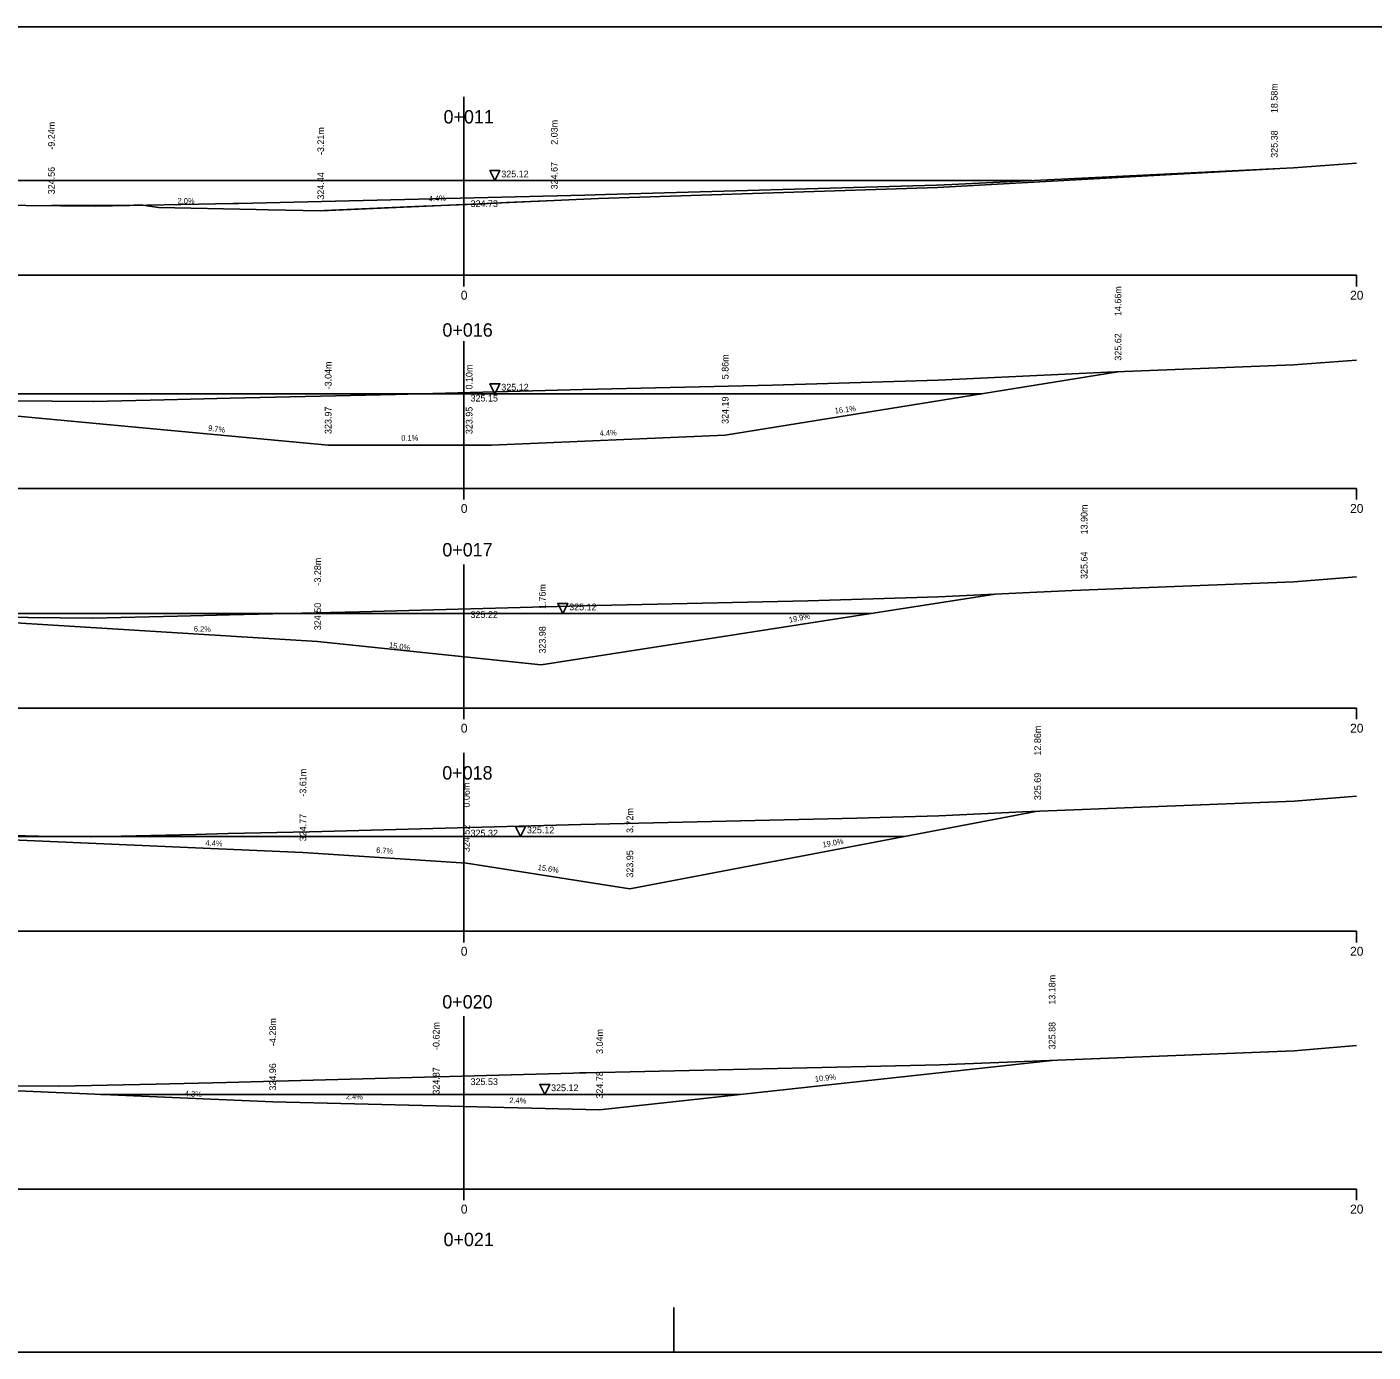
# Model space of a CAD drawing. Extents: x -557877.8 to -557804.3, y -1162285.8 to -1162256.1.
# Drawn here: x -557860.8 to -557830.63, y -1162285.8 to -1162256.1 of the extents above; entities that cross this region are included whole.
import ezdxf

# ---------------------------------------------------------------- set-up
doc = ezdxf.new("R2010")
doc.units = 0
for name, color, linetype in [('16', 7, 'Continuous'), ('21', 7, 'Continuous'), ('28', 7, 'Continuous'), ('59', 7, 'Continuous'), ('Body pricny rez', 7, 'Continuous'), ('Popis pricneho profilu', 7, 'Continuous')]:
    doc.layers.add(name, color=color, linetype=linetype)

msp = doc.modelspace()

# ---------------------------------------------------------------- linework, layer by layer
for p, q in [((-557804.302, -1162256.102), (-557877.802, -1162256.102)), ((-557846.302, -1162285.802), (-557846.302, -1162284.802)), ((-557877.802, -1162285.802), (-557804.302, -1162285.802))]:
    msp.add_line(p, q)
for points in [[(-557871.005, -1162259.545), (-557864.464, -1162260.043), (-557864.118, -1162260.057), (-557862.37, -1162260.09), (-557859.263, -1162260.117), (-557856.183, -1162260.062), (-557856.133, -1162260.062), (-557856.051, -1162260.06), (-557848.291, -1162259.873), (-557847.829, -1162259.856), (-557840.415, -1162259.648), (-557840.07, -1162259.632), (-557832.415, -1162259.263), (-557831.005, -1162259.154)], [(-557860.246, -1162260.103), (-557858.4, -1162260.098), (-557858.196, -1162260.095), (-557857.844, -1162260.15), (-557855.661, -1162260.194), (-557855.389, -1162260.199), (-557854.211, -1162260.223), (-557854.132, -1162260.219), (-557852.105, -1162260.13), (-557850.74, -1162260.071), (-557850.048, -1162260.04), (-557848.979, -1162259.993), (-557847.99, -1162259.95), (-557840.395, -1162259.701), (-557832.845, -1162259.284)], [(-557870.994, -1162259.546), (-557838.275, -1162259.546)], [(-557848.979, -1162259.993), (-557854.211, -1162260.223)], [(-557848.979, -1162259.993), (-557854.211, -1162260.223)], [(-557871.005, -1162263.973), (-557869.084, -1162264.121), (-557863.687, -1162264.471), (-557863.682, -1162264.471), (-557861.146, -1162264.48), (-557859.312, -1162264.494), (-557859.307, -1162264.494), (-557857.717, -1162264.456), (-557856.24, -1162264.425), (-557852.539, -1162264.339), (-557848.349, -1162264.225), (-557844.087, -1162264.128), (-557840.375, -1162264.022), (-557836.581, -1162263.841), (-557832.414, -1162263.676), (-557831.005, -1162263.567)], [(-557845.149, -1162265.249), (-557836.348, -1162263.832)], [(-557854.045, -1162265.475), (-557867.49, -1162264.224)], [(-557866.422, -1162264.324), (-557839.401, -1162264.324)], [(-557850.382, -1162265.478), (-557854.045, -1162265.475)], [(-557850.382, -1162265.478), (-557854.045, -1162265.475)], [(-557850.382, -1162265.478), (-557845.149, -1162265.249)], [(-557850.382, -1162265.478), (-557845.149, -1162265.249)], [(-557871.005, -1162268.839), (-557869.944, -1162268.921), (-557862.864, -1162269.33), (-557862.864, -1162269.33), (-557862.858, -1162269.33), (-557860.77, -1162269.339), (-557859.335, -1162269.35), (-557859.329, -1162269.35), (-557857.423, -1162269.305), (-557856.259, -1162269.28), (-557853.342, -1162269.212), (-557848.362, -1162269.077), (-557843.297, -1162268.961), (-557840.368, -1162268.878), (-557837.376, -1162268.736), (-557832.408, -1162268.539), (-557831.005, -1162268.43)], [(-557849.271, -1162270.399), (-557839.102, -1162268.818)], [(-557854.281, -1162269.873), (-557867.102, -1162269.085)], [(-557864.436, -1162269.249), (-557841.875, -1162269.249)], [(-557849.271, -1162270.399), (-557854.281, -1162269.873)], [(-557871.005, -1162273.756), (-557866.633, -1162274.079), (-557866.633, -1162274.079), (-557866.626, -1162274.079), (-557860.248, -1162274.247), (-557859.367, -1162274.253), (-557859.359, -1162274.253), (-557857.014, -1162274.198), (-557856.286, -1162274.182), (-557854.46, -1162274.14), (-557848.38, -1162273.975), (-557842.196, -1162273.834), (-557840.359, -1162273.781), (-557838.482, -1162273.692), (-557832.4, -1162273.451), (-557831.005, -1162273.343)], [(-557847.285, -1162275.418), (-557838.148, -1162273.682)], [(-557847.285, -1162275.418), (-557838.148, -1162273.682)], [(-557854.611, -1162274.603), (-557866.633, -1162274.079)], [(-557862.728, -1162274.249), (-557841.132, -1162274.249)], [(-557850.948, -1162274.847), (-557854.611, -1162274.603)], [(-557850.948, -1162274.847), (-557854.611, -1162274.603)], [(-557850.948, -1162274.847), (-557847.285, -1162275.418)], [(-557850.948, -1162274.847), (-557847.285, -1162275.418)], [(-557871.005, -1162279.36), (-557864.773, -1162279.805), (-557864.6, -1162279.814), (-557864.591, -1162279.815), (-557864.11, -1162279.821), (-557860.084, -1162279.844), (-557860.076, -1162279.845), (-557857.908, -1162279.794), (-557856.326, -1162279.761), (-557848.559, -1162279.549), (-557848.413, -1162279.546), (-557848.274, -1162279.543), (-557840.34, -1162279.365), (-557839.969, -1162279.351), (-557832.396, -1162279.05), (-557831.005, -1162278.934)], [(-557847.962, -1162280.37), (-557837.823, -1162279.266)], [(-557847.962, -1162280.37), (-557837.823, -1162279.266)], [(-557855.288, -1162280.192), (-557863.955, -1162279.822)], [(-557859.146, -1162280.027), (-557844.812, -1162280.027)], [(-557851.625, -1162280.281), (-557855.288, -1162280.192)], [(-557851.625, -1162280.281), (-557855.288, -1162280.192)], [(-557851.625, -1162280.281), (-557847.962, -1162280.37)], [(-557851.625, -1162280.281), (-557847.962, -1162280.37)]]:
    msp.add_lwpolyline(points)
for points in [[(-557850.309, -1162259.546), (-557850.421, -1162259.321), (-557850.196, -1162259.321)], [(-557850.309, -1162264.324), (-557850.421, -1162264.099), (-557850.196, -1162264.099)], [(-557848.787, -1162269.249), (-557848.9, -1162269.024), (-557848.675, -1162269.024)], [(-557849.734, -1162274.249), (-557849.846, -1162274.024), (-557849.621, -1162274.024)], [(-557849.192, -1162280.027), (-557849.305, -1162279.802), (-557849.08, -1162279.802)]]:
    msp.add_lwpolyline(points, close=True)
at = {"layer": '16'}
for p, q in [((-557871.005, -1162261.666), (-557831.005, -1162261.666)), ((-557871.005, -1162266.444), (-557831.005, -1162266.444)), ((-557871.005, -1162271.369), (-557831.005, -1162271.369)), ((-557871.005, -1162276.369), (-557831.005, -1162276.369)), ((-557871.005, -1162282.147), (-557831.005, -1162282.147))]:
    msp.add_line(p, q, dxfattribs=at)
at = {"layer": '28'}
for p, q in [((-557851.005, -1162257.666), (-557851.005, -1162261.666)), ((-557851.005, -1162263.146), (-557851.005, -1162266.444)), ((-557851.005, -1162268.153), (-557851.005, -1162271.369)), ((-557851.005, -1162272.369), (-557851.005, -1162276.369)), ((-557851.005, -1162278.271), (-557851.005, -1162282.147))]:
    msp.add_line(p, q, dxfattribs=at)
at = {"layer": '59'}
for p, q in [((-557851.005, -1162261.916), (-557851.005, -1162261.666)), ((-557831.005, -1162261.916), (-557831.005, -1162261.666)), ((-557851.005, -1162266.694), (-557851.005, -1162266.444)), ((-557831.005, -1162266.694), (-557831.005, -1162266.444)), ((-557851.005, -1162271.619), (-557851.005, -1162271.369)), ((-557831.005, -1162271.619), (-557831.005, -1162271.369)), ((-557851.005, -1162276.619), (-557851.005, -1162276.369)), ((-557831.005, -1162276.619), (-557831.005, -1162276.369)), ((-557851.005, -1162282.397), (-557851.005, -1162282.147)), ((-557831.005, -1162282.397), (-557831.005, -1162282.147))]:
    msp.add_line(p, q, dxfattribs=at)

# ---------------------------------------------------------------- texts
for s, height, p in [('0+011', 0.3, (-557851.46, -1162258.266)), ('325.12', 0.15, (-557850.166, -1162259.472)), ('0+016', 0.3, (-557851.485, -1162263.044)), ('325.12', 0.15, (-557850.166, -1162264.251)), ('0+017', 0.3, (-557851.487, -1162267.969)), ('325.12', 0.15, (-557848.645, -1162269.176)), ('0+018', 0.3, (-557851.488, -1162272.969)), ('325.12', 0.15, (-557849.591, -1162274.176)), ('0+020', 0.3, (-557851.488, -1162278.102)), ('325.12', 0.15, (-557849.05, -1162279.954)), ('0+021', 0.3, (-557851.46, -1162283.427))]:
    msp.add_text(s, height=height).set_placement(p)
for s, rotation, p in [('16.1%', 6.8723, (-557842.687, -1162264.767)), ('9.7%', 352.9905, (-557856.74, -1162265.151))]:
    msp.add_text(s, height=0.125, rotation=rotation).set_placement(p)
at = {"layer": '16'}
for s, rotation, p in [('2.0%', 358.8604, (-557857.422, -1162260.059)), ('4.4%', 2.5086, (-557851.788, -1162260.016)), ('4.4%', 2.5086, (-557847.959, -1162265.272)), ('0.1%', 359.9393, (-557852.407, -1162265.376)), ('19.9%', 11.2497, (-557843.707, -1162269.455)), ('6.2%', 357.3014, (-557857.057, -1162269.65)), ('15.0%', 351.4967, (-557852.689, -1162270.011)), ('19.0%', 10.7549, (-557842.955, -1162274.495)), ('4.4%', 357.2549, (-557856.797, -1162274.45)), ('6.7%', 356.1861, (-557852.973, -1162274.612)), ('15.6%', 351.1463, (-557849.356, -1162274.995)), ('10.9%', 6.2156, (-557843.133, -1162279.744)), ('4.3%', 357.0992, (-557857.26, -1162280.067)), ('2.4%', 358.6034, (-557853.65, -1162280.132)), ('2.4%', 358.6034, (-557849.987, -1162280.221))]:
    msp.add_text(s, height=0.125, rotation=rotation, dxfattribs=at).set_placement(p)
at = {"layer": '21'}
for s, p in [('0', (-557851.072, -1162262.216)), ('20', (-557831.145, -1162262.216)), ('0', (-557851.072, -1162266.994)), ('20', (-557831.145, -1162266.994)), ('0', (-557851.072, -1162271.919)), ('20', (-557831.145, -1162271.919)), ('0', (-557851.072, -1162276.919)), ('20', (-557831.145, -1162276.919)), ('0', (-557851.072, -1162282.697)), ('20', (-557831.145, -1162282.697))]:
    msp.add_text(s, height=0.2, dxfattribs=at).set_placement(p)
at = {"layer": '59'}
for s, p in [('324.73', (-557850.855, -1162260.138)), ('325.15', (-557850.855, -1162264.497)), ('325.22', (-557850.855, -1162269.349)), ('325.32', (-557850.855, -1162274.246)), ('325.53', (-557850.855, -1162279.816))]:
    msp.add_text(s, height=0.15, dxfattribs=at).set_placement(p)
at = {"layer": 'Body pricny rez'}
for p in [(-557860.247, -1162260.103), (-557860.247, -1162260.103), (-557851.005, -1162259.939), (-557851.005, -1162259.939), (-557848.979, -1162259.994), (-557848.979, -1162259.994), (-557854.212, -1162260.223), (-557854.212, -1162260.223), (-557839.811, -1162263.996), (-557839.811, -1162263.996), (-557857.559, -1162264.454), (-557857.559, -1162264.454), (-557854.045, -1162265.475), (-557854.045, -1162265.475), (-557850.382, -1162265.479), (-557850.382, -1162265.479), (-557845.149, -1162265.25), (-557845.149, -1162265.25), (-557839.102, -1162268.818), (-557839.102, -1162268.818), (-557857.52, -1162269.308), (-557857.52, -1162269.308), (-557854.282, -1162269.874), (-557854.282, -1162269.874), (-557838.149, -1162273.683), (-557838.149, -1162273.683), (-557857.83, -1162274.218), (-557857.83, -1162274.218), (-557854.612, -1162274.604), (-557854.612, -1162274.604), (-557850.949, -1162274.848), (-557850.949, -1162274.848), (-557847.286, -1162275.418), (-557847.286, -1162275.418), (-557837.823, -1162279.267), (-557837.823, -1162279.267), (-557858.123, -1162279.802), (-557858.123, -1162279.802), (-557855.288, -1162280.192), (-557855.288, -1162280.192), (-557851.625, -1162280.281), (-557851.625, -1162280.281), (-557847.962, -1162280.371), (-557847.962, -1162280.371)]:
    msp.add_text('+', height=0.001, dxfattribs=at).set_placement(p)
at = {"layer": 'Popis pricneho profilu'}
for s, p in [('18.58m', (-557832.77, -1162258.034)), ('-9.24m', (-557860.171, -1162258.853)), ('2.03m', (-557848.904, -1162258.743)), ('-3.21m', (-557854.136, -1162258.973)), ('325.38', (-557832.77, -1162259.034)), ('324.67', (-557848.904, -1162259.743)), ('324.56', (-557860.171, -1162259.853)), ('324.44', (-557854.136, -1162259.973)), ('14.66m', (-557836.27, -1162262.582)), ('325.62', (-557836.27, -1162263.582)), ('-3.04m', (-557853.97, -1162264.225)), ('0.10m', (-557850.811, -1162264.228)), ('5.86m', (-557845.074, -1162263.999)), ('323.97', (-557853.97, -1162265.225)), ('323.95', (-557850.811, -1162265.228)), ('324.19', (-557845.074, -1162264.999)), ('13.90m', (-557837.03, -1162267.475)), ('325.64', (-557837.03, -1162268.475)), ('-3.28m', (-557854.206, -1162268.623)), ('1.76m', (-557849.17, -1162269.148)), ('324.50', (-557854.206, -1162269.623)), ('323.98', (-557849.17, -1162270.148)), ('12.86m', (-557838.073, -1162272.432)), ('-3.61m', (-557854.536, -1162273.353)), ('0.06m', (-557850.873, -1162273.597)), ('325.69', (-557838.073, -1162273.432)), ('3.72m', (-557847.21, -1162274.168)), ('324.77', (-557854.536, -1162274.353)), ('324.52', (-557850.873, -1162274.597)), ('323.95', (-557847.21, -1162275.168)), ('13.18m', (-557837.748, -1162278.016)), ('-4.28m', (-557855.213, -1162278.942)), ('-0.62m', (-557851.55, -1162279.031)), ('325.88', (-557837.748, -1162279.016)), ('3.04m', (-557847.887, -1162279.12)), ('324.96', (-557855.213, -1162279.942)), ('324.87', (-557851.55, -1162280.031)), ('324.78', (-557847.887, -1162280.12))]:
    msp.add_text(s, height=0.15, rotation=90, dxfattribs=at).set_placement(p)

doc.saveas('drawing.dxf')
